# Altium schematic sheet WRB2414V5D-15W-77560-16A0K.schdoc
size 277 x 190 mm; Device: default297x210; Symbol: default297x210; Name: default297x210; Date: 2026.03.23; Rev: V1.0; Size: "A4"; Id: /; File: WRB2414V5D-15W-77560-16A0K; Sheet: /
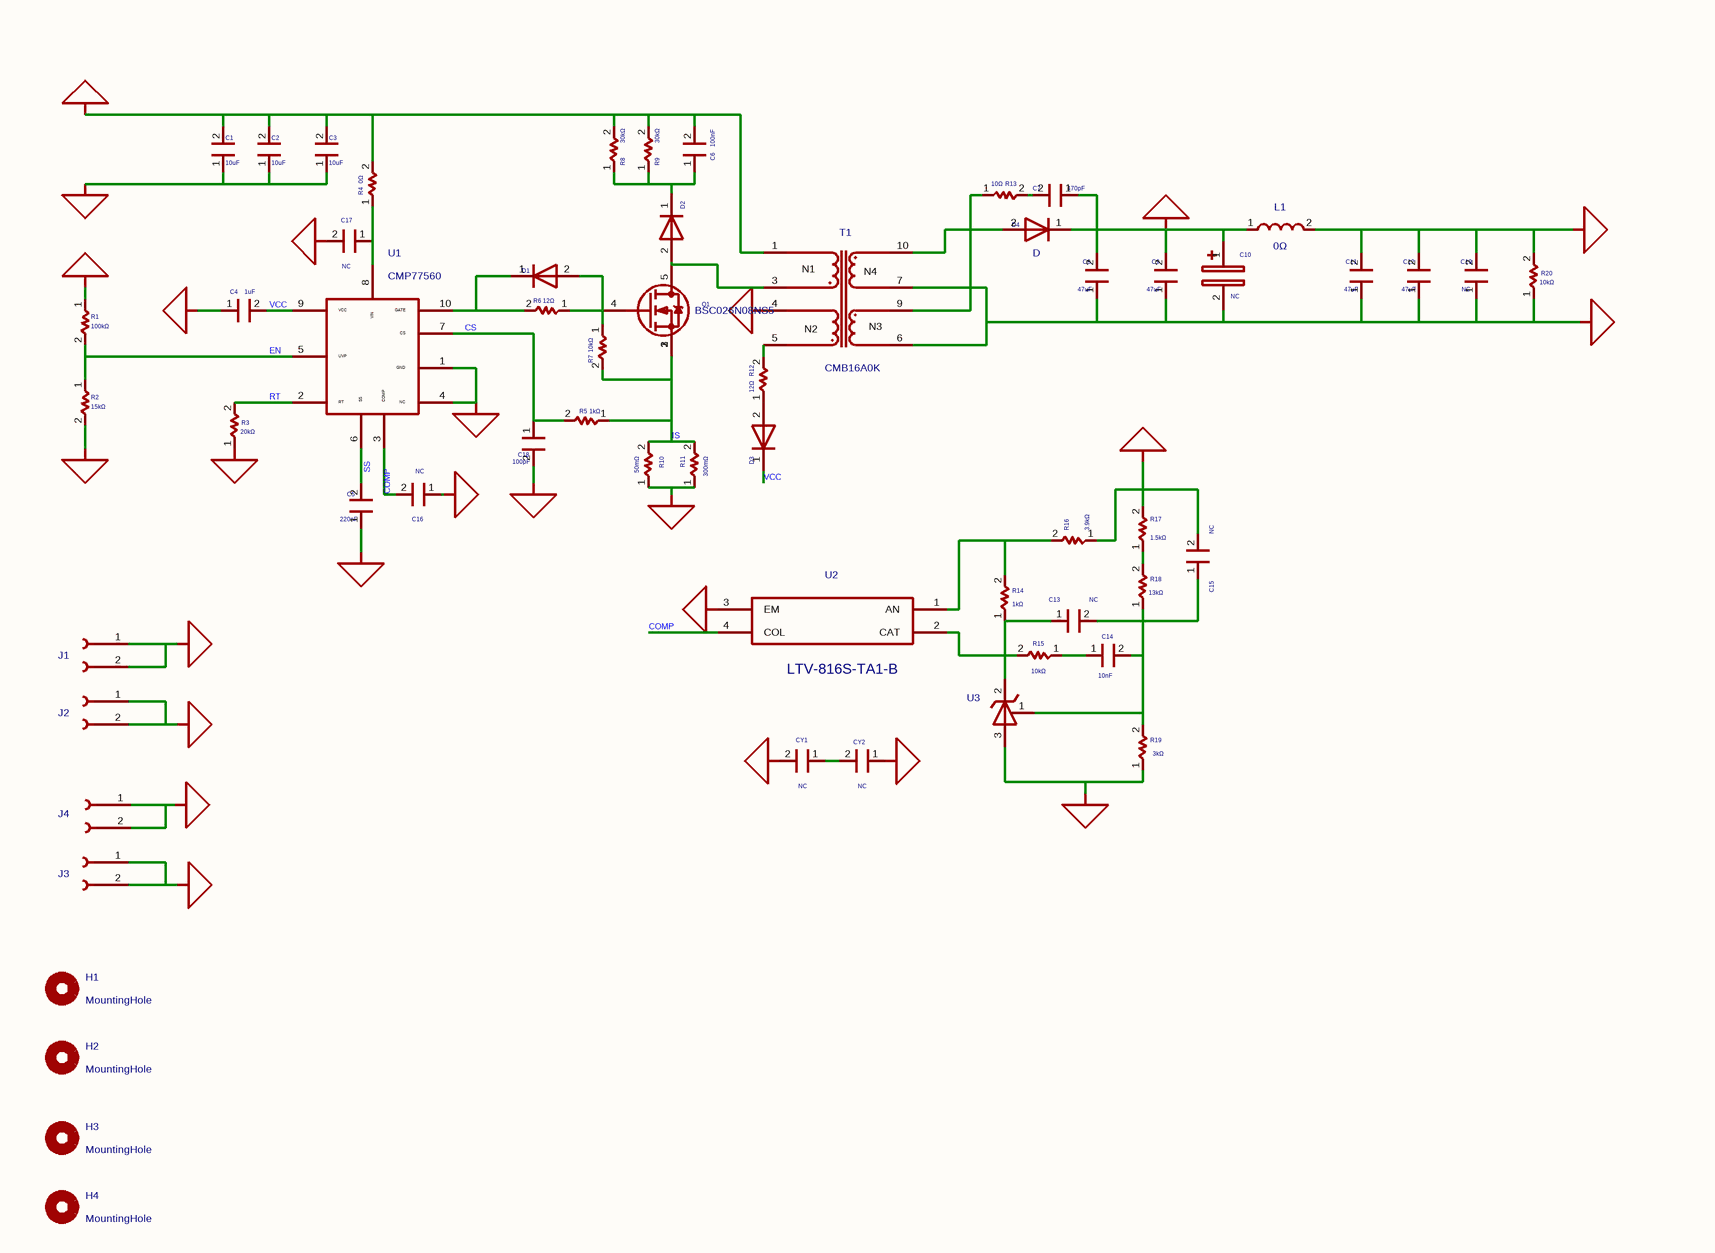
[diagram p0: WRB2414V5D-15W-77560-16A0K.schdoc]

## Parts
C1  10uF  [MYLibrary:C1206A]
C2  10uF  [MYLibrary:C1206A]
C3  10uF  [MYLibrary:C1206A]
C4  1uF  [MYLibrary:C0603]
C5  220nF  [MYLibrary:C0603]
C6  100nF  [MYLibrary:C0805]
C7  470pF  [MYLibrary:C0805]
C8  47uF  [MYLibrary:C1206A]
C9  47uF  [MYLibrary:C1206A]
C10  value NC  [Capacitor_THT:CP_Radial_D8.0mm_P3.50mm]  (hidden comment: Device_C_Polarized)
C11  47uF  [MYLibrary:C1206A]
C12  47uF  [MYLibrary:C1206A]
C13  value NC  [MYLibrary:C0603]  (hidden comment: Coileasy library_C)
C14  10nF  [MYLibrary:C0603]
C15  value NC  [MYLibrary:C0603]  (hidden comment: Coileasy library_C)
C16  value NC  [MYLibrary:C0603]  (hidden comment: Coileasy library_C)
C17  value NC  [MYLibrary:C0603]  (hidden comment: Coileasy library_C)
C18  100pF  [MYLibrary:C0603]
C19  value NC  [MYLibrary:C0603]  (hidden comment: Coileasy library_C)
CY1  value NC  [MYLibrary:C1206]  (hidden comment: Coileasy library_C)
CY2  value NC  [MYLibrary:C1206]  (hidden comment: Coileasy library_C)
D1  B5819WS  [Diode_SMD:D_SOD-323_HandSoldering]  (value not drawn)
D2  DSK120  [MYLibrary:SOD-123-323]  (value not drawn)
D3  DSK120  [MYLibrary:SOD-123-323]  (value not drawn)
D4  value D  [Diode_SMD:D_PowerDI-5]  (hidden comment: SS5U100)
H1  value MountingHole  [MountingHole:MountingHole_3.2mm_M3]  (hidden comment: Mechanical_MountingHole)
H2  value MountingHole  [MountingHole:MountingHole_3.2mm_M3]  (hidden comment: Mechanical_MountingHole)
H3  value MountingHole  [MountingHole:MountingHole_3.2mm_M3]  (hidden comment: Mechanical_MountingHole)
H4  value MountingHole  [MountingHole:MountingHole_3.2mm_M3]  (hidden comment: Mechanical_MountingHole)
J1  HX PZ2.54-1x2P ZZ  [Connector_PinHeader_2.54mm:PinHeader_1x02_P2.54mm_Vertical]  (value not drawn)
J2  HX PZ2.54-1x2P ZZ  [Connector_PinHeader_2.54mm:PinHeader_1x02_P2.54mm_Vertical]  (value not drawn)
J3  HX PZ2.54-1x2P ZZ  [Connector_PinHeader_2.54mm:PinHeader_1x02_P2.54mm_Vertical]  (value not drawn)
J4  HX PZ2.54-1x2P ZZ  [Connector_PinHeader_2.54mm:PinHeader_1x02_P2.54mm_Vertical]  (value not drawn)
L1  0Ω  [Inductor_SMD:L_APV_ANR4018]
Q1  value BSC026N08NS5  [Package_TO_SOT_SMD:TDSON-8-1]  (hidden comment: CRSM120N10L2)
R1  100kΩ  [MYLibrary:R0603]
R2  15kΩ  [MYLibrary:R0603]
R3  20kΩ  [MYLibrary:R0603]
R4  0Ω  [MYLibrary:R0603]
R5  1kΩ  [MYLibrary:R0603]
R6  12Ω  [MYLibrary:R0603]
R7  10kΩ  [MYLibrary:R0603]
R8  30kΩ  [MYLibrary:R1206A]
R9  30kΩ  [MYLibrary:R1206A]
R10  50mΩ  [MYLibrary:R1206]
R11  value 300mΩ  [MYLibrary:R1206]  (hidden comment: Coileasy library_R)
R12  12Ω  [coileasy:R_0603]
R13  10Ω  [MYLibrary:R1206A]
R14  1kΩ  [MYLibrary:R0603]
R15  10kΩ  [MYLibrary:R0603]
R16  3.9kΩ  [MYLibrary:R0603]
R17  1.5kΩ  [MYLibrary:R0603]
R18  13kΩ  [MYLibrary:R0603]
R19  3kΩ  [MYLibrary:R0603]
R20  10kΩ  [MYLibrary:R0603]
T1  value CMB16A0K  [My Library:CMB16A0K]  (hidden comment: Library_CMB16A0K)
U1  value CMP77560  [Package_SO:MSOP-10_3x3mm_P0.5mm]  (hidden comment: Library_CMP77560)
U2  LTV-816S-TA1-B  [kicad_community_lib:PC817B__Slkor]
U3  CJ431  [Package_TO_SOT_SMD:SOT-23]  (value not drawn)

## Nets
GND1: C1.1 C2.1 C3.1 C4.1 C5.1 C16.1 C17.2 C18.2 CY1.2 J2.1(Pin_1) J2.2(Pin_2) R2.2 R3.1 R10.1 R11.1 T1.4 U1.1(GND) U1.4(NC) U2.3(EM)
GND2: C8.1 C9.1 C10.2 C11.1 C12.1 C19.1 CY2.1 J3.1(Pin_1) J3.2(Pin_2) R19.1 R20.1 T1.6 T1.7 U3.3
VIN: C1.2 C2.2 C3.2 C6.2 J1.1(Pin_1) J1.2(Pin_2) R1.1 R4.2 R8.2 R9.2 T1.1
VO: C11.2 C12.2 C19.2 J4.1(Pin_1) J4.2(Pin_2) L1.2 R20.2
VOUT: C7.1 C8.2 C9.2 C10.1 C15.2 D4.1(K) L1.1 R16.1 R17.2
COMP: C16.2 U1.3(COMP) U2.4(COL)
CS: C18.1 R5.2 U1.7(CS)
EN: R1.2 R2.1 U1.5(UVP)
IS: Q1.1(S) Q1.2(S) Q1.3(S) R5.1 R7.2 R10.2 R11.2
RT: R3.2 U1.2(RT)
SS: C5.2 U1.6(SS)
VCC: C4.2 D3.1(K) U1.9(VCC)
NetC6_1: C6.1 D2.1(K) R8.1 R9.1
NetC7_2: C7.2 R13.2
NetC13_1: C13.1 R14.1 R15.2 U2.2(CAT) U3.2
NetC13_2: C13.2 C14.2 C15.1 R18.1 R19.2 U3.1
NetC14_1: C14.1 R15.1
NetC17_1: C17.1 R4.1 U1.8(VIN)
NetCY1_1: CY1.1 CY2.2
NetD1_1: D1.1(K) R6.2 U1.10(GATE)
NetD1_2: D1.2(A) Q1.4(G) R6.1 R7.1
NetD2_2: D2.2(A) Q1.5(D) T1.3
NetD3_2: D3.2(A) R12.1
NetD4_2: D4.2(A) R13.1 T1.9 T1.10
NetR12_2: R12.2 T1.5
NetR14_2: R14.2 R16.2 U2.1(AN)
NetR17_1: R17.1 R18.2

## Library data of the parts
C1-C3 = 1206X106K500NT: 容值:10uF;精度:±10%;额定电压:50V;温度系数:X5R;; Manufacturer: FH(风华); Symbol: Coileasy library_C; Add into BOM: yes; 3D Model: e4be705b945545a48e666415e3682bd8; 3D Model Transform: 125.984,62.992,0,0,0,0,0,0,0; Tolerance: ±10%; Voltage Rating: 50V; Temperature Coefficient: X5R; ki_keywords: cap capacitor; ki_fp_filters: C_*; ModelName: C1206_L3.2-W1.6-H1.3
C4 = 0603B105K250NT: 容值:1uF;精度:±10%;额定电压:25V;温度系数:X7R;; Manufacturer: FH(风华); Symbol: Coileasy library_C; Add into BOM: yes; 3D Model: ac125912035d415993ca9572d50418b1; 3D Model Transform: 62.992,31.496,0,0,0,0,0,0,0; Tolerance: ±10%; Voltage Rating: 25V; Temperature Coefficient: X7R; ki_keywords: cap capacitor; ki_fp_filters: C_*; UniqueId: 623e2bb2442f04df; ModelName: C0603_L1.6-W0.8-H0.8
C5 = 0603B224K500NT: 容值:220nF;精度:±10%;额定电压:50V;温度系数:X7R;; Manufacturer: FH(风华); Symbol: Coileasy library_C; Add into BOM: yes; 3D Model: ac125912035d415993ca9572d50418b1; 3D Model Transform: 62.992,31.496,0,0,0,0,0,0,0; Tolerance: ±10%; Voltage Rating: 50V; Temperature Coefficient: X7R; ki_keywords: cap capacitor; ki_fp_filters: C_*; ModelName: C0603_L1.6-W0.8-H0.8
C6 = 0805B104K101NT: 容值:100nF;精度:±10%;额定电压:100V;温度系数:X7R;; Manufacturer: FH(风华); Symbol: Coileasy library_C; Add into BOM: yes; 3D Model: 1ba041120af144c991958decab20d241; 3D Model Transform: 78.74,51.181,0,0,0,0,0,0.0005,0; Tolerance: ±10%; Voltage Rating: 100V; Temperature Coefficient: X7R; ki_keywords: cap capacitor; ki_fp_filters: C_*; ModelName: C0805_L2.0-W1.3-H1.3
C7 = CC0805JRX7RABB471: 容值:470pF;精度:±5%;额定电压:200V;温度系数:X7R;; Manufacturer: YAGEO(国巨); Symbol: Coileasy library_C; Add into BOM: yes; 3D Model: 1ba041120af144c991958decab20d241; 3D Model Transform: 78.74,51.181,0,0,0,0,0,0.0005,0; Tolerance: ±5%; Voltage Rating: 200V; Temperature Coefficient: X7R; ki_keywords: cap capacitor; ki_fp_filters: C_*; UniqueId: 3007ca2539a35480; ModelName: C0805_L2.0-W1.3-H1.3
C8 = C3216X5R1E476MTJ00E: 容值:47uF;精度:±20%;额定电压:25V;温度系数:X5R;; Manufacturer: TDK; Symbol: Coileasy library_C; Add into BOM: yes; 3D Model: e4be705b945545a48e666415e3682bd8; 3D Model Transform: 125.984,62.992,0,0,0,0,0,0,0; Tolerance: ±20%; Voltage Rating: 25V; Temperature Coefficient: X5R; ki_keywords: cap capacitor; ki_fp_filters: C_*; UniqueId: 878ab3ab0cce2757; ModelName: C1206_L3.2-W1.6-H1.3
C9 = C3216X5R1E476MTJ00E: 容值:47uF;精度:±20%;额定电压:25V;温度系数:X5R;; Manufacturer: TDK; Symbol: Coileasy library_C; Add into BOM: yes; 3D Model: e4be705b945545a48e666415e3682bd8; 3D Model Transform: 125.984,62.992,0,0,0,0,0,0,0; Tolerance: ±20%; Voltage Rating: 25V; Temperature Coefficient: X5R; ki_keywords: cap capacitor; ki_fp_filters: C_*; UniqueId: 60e6893b044e2f17; ModelName: C1206_L3.2-W1.6-H1.3
C10 = Device_C_Polarized: NC; Add into BOM: no; ki_keywords: cap capacitor; ki_fp_filters: CP_*; UniqueId: c1764753ee6525b4; Attribute1: C10
C11 = C3216X5R1E476MTJ00E: 容值:47uF;精度:±20%;额定电压:25V;温度系数:X5R;; Manufacturer: TDK; Symbol: Coileasy library_C; Add into BOM: yes; 3D Model: e4be705b945545a48e666415e3682bd8; 3D Model Transform: 125.984,62.992,0,0,0,0,0,0,0; Tolerance: ±20%; Voltage Rating: 25V; Temperature Coefficient: X5R; ki_keywords: cap capacitor; ki_fp_filters: C_*; UniqueId: b49c3108c5288e9f; ModelName: C1206_L3.2-W1.6-H1.3
C12 = C3216X5R1E476MTJ00E: 容值:47uF;精度:±20%;额定电压:25V;温度系数:X5R;; Manufacturer: TDK; Symbol: Coileasy library_C; Add into BOM: yes; 3D Model: e4be705b945545a48e666415e3682bd8; 3D Model Transform: 125.984,62.992,0,0,0,0,0,0,0; Tolerance: ±20%; Voltage Rating: 25V; Temperature Coefficient: X5R; ki_keywords: cap capacitor; ki_fp_filters: C_*; ModelName: C1206_L3.2-W1.6-H1.3
C13 = Coileasy library_C: NC; Add into BOM: no; ki_keywords: cap capacitor; ki_fp_filters: C_*; UniqueId: 8d11a04c32f33369; Attribute1: C4
C14 = 0603B103K500NT: 容值:10nF;精度:±10%;额定电压:50V;温度系数:X7R;; Manufacturer: FH(风华); Symbol: Coileasy library_C; Add into BOM: yes; 3D Model: ac125912035d415993ca9572d50418b1; 3D Model Transform: 62.992,31.496,0,0,0,0,0,0,0; Tolerance: ±10%; Voltage Rating: 50V; Temperature Coefficient: X7R; ki_keywords: cap capacitor; ki_fp_filters: C_*; ModelName: C0603_L1.6-W0.8-H0.8
C15 = Coileasy library_C: NC; Add into BOM: no; ki_keywords: cap capacitor; ki_fp_filters: C_*; UniqueId: 4a0fa0f8d5a09ecc; Attribute1: C4
C16 = Coileasy library_C: NC; Add into BOM: no; ki_keywords: cap capacitor; ki_fp_filters: C_*; Attribute1: C4
C17 = Coileasy library_C: NC; Add into BOM: no; ki_keywords: cap capacitor; ki_fp_filters: C_*; UniqueId: 5e7964c847a08933; Attribute1: C4
C18 = 0603B101K500NT: 容值:100pF;精度:±10%;额定电压:50V;温度系数:X7R;; Manufacturer: FH(风华); Symbol: Coileasy library_C; Add into BOM: yes; 3D Model: ac125912035d415993ca9572d50418b1; 3D Model Transform: 62.992,31.496,0,0,0,0,0,0,0; Tolerance: ±10%; Voltage Rating: 50V; Temperature Coefficient: X7R; ki_keywords: cap capacitor; ki_fp_filters: C_*; UniqueId: 9b976857f3e39318; ModelName: C0603_L1.6-W0.8-H0.8
C19 = Coileasy library_C: NC; ki_keywords: cap capacitor; ki_fp_filters: C_*; Attribute1: C4; AddInBom: yes
CY1 = Coileasy library_C: NC; Add into BOM: no; ki_keywords: cap capacitor; ki_fp_filters: C_*; UniqueId: 2a04cf09b0b94441; Attribute1: CY2
CY2 = Coileasy library_C: NC; Add into BOM: no; ki_keywords: cap capacitor; ki_fp_filters: C_*; UniqueId: 380dccfd22159ce2; Attribute1: CY2
D1 = B5819WS_C64886: 二极管配置:独立式;正向压降(Vf):900mV@3A;直流反向耐压(Vr):40V;整流电流:1A;; Manufacturer: MDD(辰达半导体); Symbol: Coileasy library_D; Add into BOM: yes; 3D Model: 7459fe65e23146c0a8d836e46a0add72; 3D Model Transform: 104.3305,51.181,0,0,0,0,0,0,0; Diode Configuration: 独立式; Voltage - DC Reverse(Vr): 40V; Current - Rectified: 1A; Reverse Leakage Current (Ir): 1mA@40V; Operating Junction Temperature Range: -55℃~+125℃; Non-Repetitive Peak Forward Surge Current: 25A; Value: D; ki_keywords: diode; ki_fp_filters: TO-???* *_Diode_* *SingleDiode* D_*; ModelName: SOD-323_L1.8-W1.3-LS2.5-RD
D2 = DSK120_C364269: 二极管配置:独立式;正向压降(Vf):900mV@1A;直流反向耐压(Vr):200V;整流电流:1A;; Manufacturer: MDD(辰达半导体); Symbol: Coileasy library_D; Add into BOM: yes; 3D Model: 321bc188a2eb4b418ce08d06d1c3a1f1; 3D Model Transform: 145.669,70.866,0,0,0,0,0,0,0; Diode Configuration: 独立式; Voltage - DC Reverse(Vr): 200V; Current - Rectified: 1A; Reverse Leakage Current (Ir): 100uA@200V; Operating Junction Temperature Range: -55℃~+150℃; Value: D; ki_keywords: diode; ki_fp_filters: TO-???* *_Diode_* *SingleDiode* D_*; UniqueId: fa5cd661465da5bc; ModelName: SOD-123FL_L2.8-W1.8-LS3.7-RD-1
D3 = DSK120_C364269: 二极管配置:独立式;正向压降(Vf):900mV@1A;直流反向耐压(Vr):200V;整流电流:1A;; Manufacturer: MDD(辰达半导体); Symbol: Coileasy library_D; Add into BOM: yes; 3D Model: 321bc188a2eb4b418ce08d06d1c3a1f1; 3D Model Transform: 145.669,70.866,0,0,0,0,0,0,0; Diode Configuration: 独立式; Voltage - DC Reverse(Vr): 200V; Current - Rectified: 1A; Reverse Leakage Current (Ir): 100uA@200V; Operating Junction Temperature Range: -55℃~+150℃; Value: D; ki_keywords: diode; ki_fp_filters: TO-???* *_Diode_* *SingleDiode* D_*; UniqueId: ce0e29427420bb9a; ModelName: SOD-123FL_L2.8-W1.8-LS3.7-RD-1
D4 = SS5U100: 二极管配置:独立式;正向压降(Vf):540mV@5A;直流反向耐压(Vr):100V;整流电流:5A;; Manufacturer: YANGJIE(扬杰); Symbol: Device_D; Add into BOM: yes; 3D Model: 3bdb8a8fdc2849eb9249be7ca1d649d8; 3D Model Transform: 255.905,157.48,0,0,0,0,-34.527,0,0; Diode Configuration: 独立式; Voltage - DC Reverse(Vr): 100V; Current - Rectified: 5A; Reverse Leakage Current (Ir): 200uA@100V; Operating Junction Temperature Range: -55℃~+150℃; Non-Repetitive Peak Forward Surge Current: 120A; Sim.Pins: 1=K 2=A; ki_keywords: diode; ki_fp_filters: TO-???* *_Diode_* *SingleDiode* D_*; UniqueId: 671e3575a93d22ee; ModelName: TO-277_3P-L5.4-W4.0-H1.2-LS6.5-BR
H1 = Mechanical_MountingHole: Mounting Hole without connection; ki_fp_filters: MountingHole*; UniqueId: f372d9fd695b79ed; Attribute1: H4; AddInBom: yes
H2 = Mechanical_MountingHole: Mounting Hole without connection; ki_fp_filters: MountingHole*; UniqueId: 740933c0c9dafeaa; Attribute1: H4; AddInBom: yes
H3 = Mechanical_MountingHole: Mounting Hole without connection; ki_fp_filters: MountingHole*; UniqueId: 40de206b6b7850d6; Attribute1: H4; AddInBom: yes
H4 = Mechanical_MountingHole: Mounting Hole without connection; ki_fp_filters: MountingHole*; UniqueId: 0c87e0717b354de5; Attribute1: H4; AddInBom: yes
J1 = HX PZ2.54-1x2P ZZ: 插针结构:1x2P;间距:2.54mm;行距:-;圆针/方针:方针;安装方式:直插;排数:单排;总PIN位数:2P;额定电流:3A;额定电压:1kV;配合针长度:6mm;塑高:2.5mm;端接针长度:3mm;触头材质:黄铜;触头镀层:金;工作温度:-40℃~+105℃;颜色:黑色;; Manufacturer: hanxia(韩下); Symbol: Coileasy library_Conn_01x02; Add into BOM: yes; 3D Model: c7a9f3c3e6e34627af2bf939e464cb35; 3D Model Transform: 200,100,0,0,0,0,0,0,-118.11; Pin Structure: 1x2P; Pitch: 2.54mm; Circluar Pins/Square Pins: 方针; Current Rating: 3A; Voltage Rating (Max): 1kV; Value: Conn_01x02; ki_keywords: connector; ki_fp_filters: Connector*:*_1x??_*; Origin Footprint: library:PinHeader_1x02_P2.54mm_Vertical; UniqueId: 9f49826860c2c79d; ModelName: HDR-TH_2P-P2.54-M-LI-1X2P
J2 = HX PZ2.54-1x2P ZZ: 插针结构:1x2P;间距:2.54mm;行距:-;圆针/方针:方针;安装方式:直插;排数:单排;总PIN位数:2P;额定电流:3A;额定电压:1kV;配合针长度:6mm;塑高:2.5mm;端接针长度:3mm;触头材质:黄铜;触头镀层:金;工作温度:-40℃~+105℃;颜色:黑色;; Manufacturer: hanxia(韩下); Symbol: Coileasy library_Conn_01x02; Add into BOM: yes; 3D Model: c7a9f3c3e6e34627af2bf939e464cb35; 3D Model Transform: 200,100,0,0,0,0,0,0,-118.11; Pin Structure: 1x2P; Pitch: 2.54mm; Circluar Pins/Square Pins: 方针; Current Rating: 3A; Voltage Rating (Max): 1kV; Value: Conn_01x02; ki_keywords: connector; ki_fp_filters: Connector*:*_1x??_*; Origin Footprint: library:PinHeader_1x02_P2.54mm_Vertical; UniqueId: 42913bc3a3449998; ModelName: HDR-TH_2P-P2.54-M-LI-1X2P
J3 = HX PZ2.54-1x2P ZZ: 插针结构:1x2P;间距:2.54mm;行距:-;圆针/方针:方针;安装方式:直插;排数:单排;总PIN位数:2P;额定电流:3A;额定电压:1kV;配合针长度:6mm;塑高:2.5mm;端接针长度:3mm;触头材质:黄铜;触头镀层:金;工作温度:-40℃~+105℃;颜色:黑色;; Manufacturer: hanxia(韩下); Symbol: Coileasy library_Conn_01x02; Add into BOM: yes; 3D Model: c7a9f3c3e6e34627af2bf939e464cb35; 3D Model Transform: 200,100,0,0,0,0,0,0,-118.11; Pin Structure: 1x2P; Pitch: 2.54mm; Circluar Pins/Square Pins: 方针; Current Rating: 3A; Voltage Rating (Max): 1kV; Value: Conn_01x02; ki_keywords: connector; ki_fp_filters: Connector*:*_1x??_*; Origin Footprint: library:PinHeader_1x02_P2.54mm_Vertical; UniqueId: 6ca7fcf0d18ad80e; ModelName: HDR-TH_2P-P2.54-M-LI-1X2P
J4 = HX PZ2.54-1x2P ZZ: 插针结构:1x2P;间距:2.54mm;行距:-;圆针/方针:方针;安装方式:直插;排数:单排;总PIN位数:2P;额定电流:3A;额定电压:1kV;配合针长度:6mm;塑高:2.5mm;端接针长度:3mm;触头材质:黄铜;触头镀层:金;工作温度:-40℃~+105℃;颜色:黑色;; Manufacturer: hanxia(韩下); Symbol: Coileasy library_Conn_01x02; Add into BOM: yes; 3D Model: c7a9f3c3e6e34627af2bf939e464cb35; 3D Model Transform: 200,100,0,0,0,0,0,0,-118.11; Pin Structure: 1x2P; Pitch: 2.54mm; Circluar Pins/Square Pins: 方针; Current Rating: 3A; Voltage Rating (Max): 1kV; Value: Conn_01x02; ki_keywords: connector; ki_fp_filters: Connector*:*_1x??_*; Origin Footprint: library:PinHeader_1x02_P2.54mm_Vertical; UniqueId: 048fde32f53a6793; ModelName: HDR-TH_2P-P2.54-M-LI-1X2P
L1 = RC1206FR-070RL: 电阻类型:厚膜电阻;阻值:0Ω;精度:±1%;功率:250mW;工作电压:200V;; Manufacturer: YAGEO(国巨); Symbol: Device_L; Add into BOM: yes; 3D Model: 89a1f13db2384da588040e0b3c55bf66; 3D Model Transform: 125.984,62.992,0,0,0,0,0,0,0; Type: 厚膜电阻; Tolerance: ±1%; Power(Watts): 250mW; Voltage-Supply(Max): 200V; ki_keywords: inductor choke coil reactor magnetic; ki_fp_filters: Choke_* *Coil* Inductor_* L_*; UniqueId: 2f42939b1ffc8518; ModelName: R1206_L3.2-W1.6-H0.6
Q1 = CRSM120N10L2_C20623221: 漏源电压(Vdss):100V;连续漏极电流(Id):58A;导通电阻(RDS(on)):16.9mΩ@4.5V;耗散功率(Pd):78.1W;阈值电压(Vgs(th)):2.2V@250uA;; Manufacturer: CRMICRO(华润微); Symbol: Transistor_FET_BSC026N08NS5; Add into BOM: yes; 3D Model: b529988c9acc4a02b37666fee58bfc39; 3D Model Transform: 205.511,242.1255,0,0,0,0,0,-0.001,0; Drain to Source Voltage: 100V; Current - Continuous Drain(Id): 58A; Pd - Power Dissipation: 78.1W; Gate Charge(Qg): 40nC@10V; Input Capacitance(Ciss): 2.266nF; Reverse Transfer Capacitance (Crss@Vds): 44pF; Type: N沟道; Output Capacitance(Coss): 388pF; ki_keywords: OptiMOS Power MOSFET N-MOS; ki_fp_filters: TDSON*; UniqueId: 047b734180970fea; ModelName: DFN-8_L5.9-W5.2-P1.27-LS6.2-BL
R1 = RC0603FR-07100KL: 电阻类型:厚膜电阻;阻值:100kΩ;精度:±1%;功率:100mW;最大工作电压:75V;温度系数:±100ppm/℃;; Manufacturer: YAGEO(国巨); Symbol: Coileasy library_R; Add into BOM: yes; 3D Model: fc143cca1e79419f9cd78b61e9279f08; 3D Model Transform: 31.8897,63.7794,0,90,0,0,0,0,0; Tolerance: ±1%; Power(Watts): 100mW; Overload Voltage (Max): 75V; ki_keywords: R res resistor; ki_fp_filters: R_*; ModelName: R0603
R2 = RC0603FR-0715KL: 电阻类型:厚膜电阻;阻值:15kΩ;精度:±1%;功率:100mW;工作电压:75V;温度系数:±100ppm/℃;; Manufacturer: YAGEO(国巨); Symbol: Coileasy library_R; Add into BOM: yes; 3D Model: fc143cca1e79419f9cd78b61e9279f08; 3D Model Transform: 31.8897,63.7794,0,90,0,0,0,0,0; Tolerance: ±1%; Power(Watts): 100mW; Voltage-Supply(Max): 75V; ki_keywords: R res resistor; ki_fp_filters: R_*; ModelName: R0603
R3 = RC0603FR-0720KL: 电阻类型:厚膜电阻;阻值:20kΩ;精度:±1%;功率:100mW;工作电压:75V;温度系数:±100ppm/℃;; Manufacturer: YAGEO(国巨); Symbol: Coileasy library_R; Add into BOM: yes; 3D Model: fc143cca1e79419f9cd78b61e9279f08; 3D Model Transform: 31.8897,63.7794,0,90,0,0,0,0,0; Tolerance: ±1%; Power(Watts): 100mW; Voltage-Supply(Max): 75V; ki_keywords: R res resistor; ki_fp_filters: R_*; UniqueId: 6e26aea592918673; ModelName: R0603
R4 = RC0603FR-070RL: 电阻类型:厚膜电阻;阻值:0Ω;精度:±1%;功率:100mW;工作电压:75V;温度系数:-;; Manufacturer: YAGEO(国巨); Symbol: Coileasy library_R; Add into BOM: yes; 3D Model: fc143cca1e79419f9cd78b61e9279f08; 3D Model Transform: 31.8897,63.7794,0,90,0,0,0,0,0; Tolerance: ±1%; Power(Watts): 100mW; Voltage-Supply(Max): 75V; ki_keywords: R res resistor; ki_fp_filters: R_*; UniqueId: 49359f7360e76581; ModelName: R0603
R5 = RC0603FR-071KL: 电阻类型:厚膜电阻;阻值:1kΩ;精度:±1%;功率:100mW;工作电压:75V;温度系数:±100ppm/℃;; Manufacturer: YAGEO(国巨); Symbol: Coileasy library_R; Add into BOM: yes; 3D Model: fc143cca1e79419f9cd78b61e9279f08; 3D Model Transform: 31.8897,63.7794,0,90,0,0,0,0,0; Tolerance: ±1%; Power(Watts): 100mW; Voltage-Supply(Max): 75V; ki_keywords: R res resistor; ki_fp_filters: R_*; UniqueId: 96bd3269827a783e; ModelName: R0603
R6 = RC0603FR-0712RL: 电阻类型:厚膜电阻;阻值:12Ω;精度:±1%;功率:100mW;最大工作电压:75V;温度系数:±100ppm/℃;; Manufacturer: YAGEO(国巨); Symbol: Coileasy library_R; Add into BOM: yes; 3D Model: fc143cca1e79419f9cd78b61e9279f08; 3D Model Transform: 31.8897,63.7794,0,90,0,0,0,0,0; Tolerance: ±1%; Power(Watts): 100mW; Overload Voltage (Max): 75V; ki_keywords: R res resistor; ki_fp_filters: R_*; UniqueId: c9a24d22ca7022dc; ModelName: R0603
R7 = RC0603FR-0710KL: 电阻类型:厚膜电阻;阻值:10kΩ;精度:±1%;功率:100mW;最大工作电压:75V;温度系数:±100ppm/℃;; Manufacturer: YAGEO(国巨); Symbol: Coileasy library_R; Add into BOM: yes; 3D Model: fc143cca1e79419f9cd78b61e9279f08; 3D Model Transform: 31.8897,63.7794,0,90,0,0,0,0,0; Tolerance: ±1%; Power(Watts): 100mW; Overload Voltage (Max): 75V; ki_keywords: R res resistor; ki_fp_filters: R_*; UniqueId: 01f5c70ff2630ee7; ModelName: R0603
R8 R9 = RC1206FR-0730KL: 电阻类型:厚膜电阻;阻值:30kΩ;精度:±1%;功率:250mW;工作电压:200V;温度系数:±100ppm/℃;; Manufacturer: YAGEO(国巨); Symbol: Coileasy library_R; Add into BOM: yes; 3D Model: 89a1f13db2384da588040e0b3c55bf66; 3D Model Transform: 125.984,62.992,0,0,0,0,0,0,0; Tolerance: ±1%; Power(Watts): 250mW; Voltage-Supply(Max): 200V; ki_keywords: R res resistor; ki_fp_filters: R_*; ModelName: R1206_L3.2-W1.6-H0.6
R10 = RTF06BR050FTG: 阻值:50mΩ;精度:±1%;工作电压:500mV;功率:250mW;温度系数:±300ppm/℃;; Manufacturer: FH(风华); Symbol: Coileasy library_R; Add into BOM: yes; 3D Model: 89a1f13db2384da588040e0b3c55bf66; 3D Model Transform: 125.984,62.992,0,0,0,0,0,0,0; Tolerance: ±1%; Voltage Rating: 500mV; Power(Watts): 250mW; ki_keywords: R res resistor; ki_fp_filters: R_*; UniqueId: 7663007c1f2bc029; ModelName: R1206_L3.2-W1.6-H0.6
R11 = Coileasy library_R: 300mΩ ±1% 250mW; Brand: FH; Model: RTF06KR300FTG; ki_keywords: R res resistor; ki_fp_filters: R_*; UniqueId: 069ba0dc55a84bc8; AddInBom: yes
R12 = RC0603FR-0712RL: 电阻类型:厚膜电阻;阻值:12Ω;精度:±1%;功率:100mW;最大工作电压:75V;温度系数:±100ppm/℃;; Manufacturer: YAGEO(国巨); Symbol: Coileasy library_R; Add into BOM: yes; 3D Model: fc143cca1e79419f9cd78b61e9279f08; 3D Model Transform: 31.8897,63.7794,0,90,0,0,0,0,0; Tolerance: ±1%; Power(Watts): 100mW; Overload Voltage (Max): 75V; ki_keywords: R res resistor; ki_fp_filters: R_*; UniqueId: f574a6082c36e6cb; ModelName: R0603
R13 = RC1206FR-7W10RL: 电阻类型:厚膜电阻;阻值:10Ω;精度:±1%;功率:500mW;工作电压:200V;温度系数:±200ppm/℃;; Manufacturer: YAGEO(国巨); Symbol: Coileasy library_R; Add into BOM: yes; 3D Model: 89a1f13db2384da588040e0b3c55bf66; 3D Model Transform: 125.984,62.992,0,0,0,0,0,0,0; Tolerance: ±1%; Power(Watts): 500mW; Voltage-Supply(Max): 200V; ki_keywords: R res resistor; ki_fp_filters: R_*; UniqueId: ff7631ddbc1e2fda; ModelName: R1206_L3.2-W1.6-H0.6
R14 = RC0603FR-071KL: 电阻类型:厚膜电阻;阻值:1kΩ;精度:±1%;功率:100mW;工作电压:75V;温度系数:±100ppm/℃;; Manufacturer: YAGEO(国巨); Symbol: Coileasy library_R; Add into BOM: yes; 3D Model: fc143cca1e79419f9cd78b61e9279f08; 3D Model Transform: 31.8897,63.7794,0,90,0,0,0,0,0; Tolerance: ±1%; Power(Watts): 100mW; Voltage-Supply(Max): 75V; ki_keywords: R res resistor; ki_fp_filters: R_*; UniqueId: d58291ee940aacae; ModelName: R0603
R15 R20 = RC0603FR-0710KL: 电阻类型:厚膜电阻;阻值:10kΩ;精度:±1%;功率:100mW;最大工作电压:75V;温度系数:±100ppm/℃;; Manufacturer: YAGEO(国巨); Symbol: Coileasy library_R; Add into BOM: yes; 3D Model: fc143cca1e79419f9cd78b61e9279f08; 3D Model Transform: 31.8897,63.7794,0,90,0,0,0,0,0; Tolerance: ±1%; Power(Watts): 100mW; Overload Voltage (Max): 75V; ki_keywords: R res resistor; ki_fp_filters: R_*; ModelName: R0603
R16 = RC0603FR-073K9L: 电阻类型:厚膜电阻;阻值:3.9kΩ;精度:±1%;功率:100mW;工作电压:75V;温度系数:±100ppm/℃;; Manufacturer: YAGEO(国巨); Symbol: Coileasy library_R; Add into BOM: yes; 3D Model: fc143cca1e79419f9cd78b61e9279f08; 3D Model Transform: 31.8897,63.7794,0,90,0,0,0,0,0; Tolerance: ±1%; Power(Watts): 100mW; Voltage-Supply(Max): 75V; ki_keywords: R res resistor; ki_fp_filters: R_*; UniqueId: 49a4252fe0d0166e; ModelName: R0603
R17 = RC0603FR-071K5L: 电阻类型:厚膜电阻;阻值:1.5kΩ;精度:±1%;功率:100mW;最大工作电压:75V;温度系数:±100ppm/℃;; Manufacturer: YAGEO(国巨); Symbol: Coileasy library_R; Add into BOM: yes; 3D Model: fc143cca1e79419f9cd78b61e9279f08; 3D Model Transform: 31.8897,63.7794,0,90,0,0,0,0,0; Tolerance: ±1%; Power(Watts): 100mW; Overload Voltage (Max): 75V; ki_keywords: R res resistor; ki_fp_filters: R_*; ModelName: R0603
R18 = RC0603FR-0713KL: 电阻类型:厚膜电阻;阻值:13kΩ;精度:±1%;功率:100mW;工作电压:75V;温度系数:±100ppm/℃;; Manufacturer: YAGEO(国巨); Symbol: Coileasy library_R; Add into BOM: yes; 3D Model: fc143cca1e79419f9cd78b61e9279f08; 3D Model Transform: 31.8897,63.7794,0,90,0,0,0,0,0; Tolerance: ±1%; Power(Watts): 100mW; Voltage-Supply(Max): 75V; ki_keywords: R res resistor; ki_fp_filters: R_*; UniqueId: 1bd7cdeea74e381f; ModelName: R0603
R19 = RC0603FR-073KL: 电阻类型:厚膜电阻;阻值:3kΩ;精度:±1%;功率:100mW;工作电压:75V;温度系数:±100ppm/℃;; Manufacturer: YAGEO(国巨); Symbol: Coileasy library_R; Add into BOM: yes; 3D Model: fc143cca1e79419f9cd78b61e9279f08; 3D Model Transform: 31.8897,63.7794,0,90,0,0,0,0,0; Tolerance: ±1%; Power(Watts): 100mW; Voltage-Supply(Max): 75V; ki_keywords: R res resistor; ki_fp_filters: R_*; ModelName: R0603
T1 = Library_CMB16A0K: Np:Ns=1:1  Lp=22uH; Brand: coileasy; UniqueId: cf2c480e5945250c; Attribute1: T1; AddInBom: yes
U1 = Library_CMP77560: 电源管理芯片; Brand: coileasy; UniqueId: 48a4a086d8c42a18; Attribute1: U1; AddInBom: yes
U2 = LTV-816S-TA1-B: 输入类型:DC;正向压降(Vf):1.2V;输出电流:50mA;隔离电压(Vrms):5kV;直流反向耐压(Vr):6V;负载电压:80V;输出通道数:1;集射极饱和电压(VCE(sat)):100mV@20mA,1mA;; Manufacturer: LITEON(光宝); Mpn: PC817B__Slkor; Symbol: PC817B__Slkor_PC817B__Slkor; Number of Outputs: 1; Output Current: 50mA; Output Type: 光电三极管; Reverse Voltage: 6V; Add into BOM: yes; 3D Model: 014d3d1fd7f54d9b8c0e014c102a6936; 3D Model Transform: 401.94494,181.102,0,90,0,0,0,0,0; Input type: DC; Voltage - Forward(Vf): 1.2V; Isolation Voltage(Vrms): 5kV; Load Voltage: 80V; Rise time: 4us; Fall time: 3us; Current Transfer Ratio (CTR) Minimum: 50%; Current Transfer Ratio (CTR) Maximum/Saturation Value: 600%; Total Power Dissipation(Pd): 200mW; Value: VRB2414V5D-15W-77560-16A0K; Collector Emitter Saturation Voltage: 100 mV @1mA,20mA; Current Transfer Ratio (Min): 130 %; Forward Current: 50 mA; Forward Voltage: 1.2 V; Isolation Voltage: 5 kV; Output Voltage: 35 V; Power Rating: 200 mW; UniqueId: d74c11912b695046; ModelName: SMD-4_L4.6-W6.4-H3.7-LS10.0-P2.54
U3 = CJ431_C3113: 输出类型:可调;工作电压:-;输出电压:2.5V~36V;输出电流:100mA;精度:±0.5%;; Manufacturer: CJ(江苏长电/长晶); Symbol: Coileasy library_CJ431; Add into BOM: yes; 3D Model: 89cb27a44ab2466697082bb9fd73a7d0; 3D Model Transform: 114.173,110.236,0,90,0,0,0,0,0; Output Type: 可调; Output Current: 100mA; Tolerance: ±0.5%; Temperature Coefficient: 50ppm/℃; Reference Type: 并联; Minimum Cathode Current for Regulation: 1mA; Value: ~; ki_keywords: diode; ki_fp_filters: TO-???* *_Diode_* *SingleDiode* D_*; UniqueId: eac3f191c372887e; ModelName: SOT-23-3L_L2.9-W1.6-H1.1-LS2.8-P0.95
